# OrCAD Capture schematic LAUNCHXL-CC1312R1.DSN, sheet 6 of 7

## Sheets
6 2_Peripherals: size A3
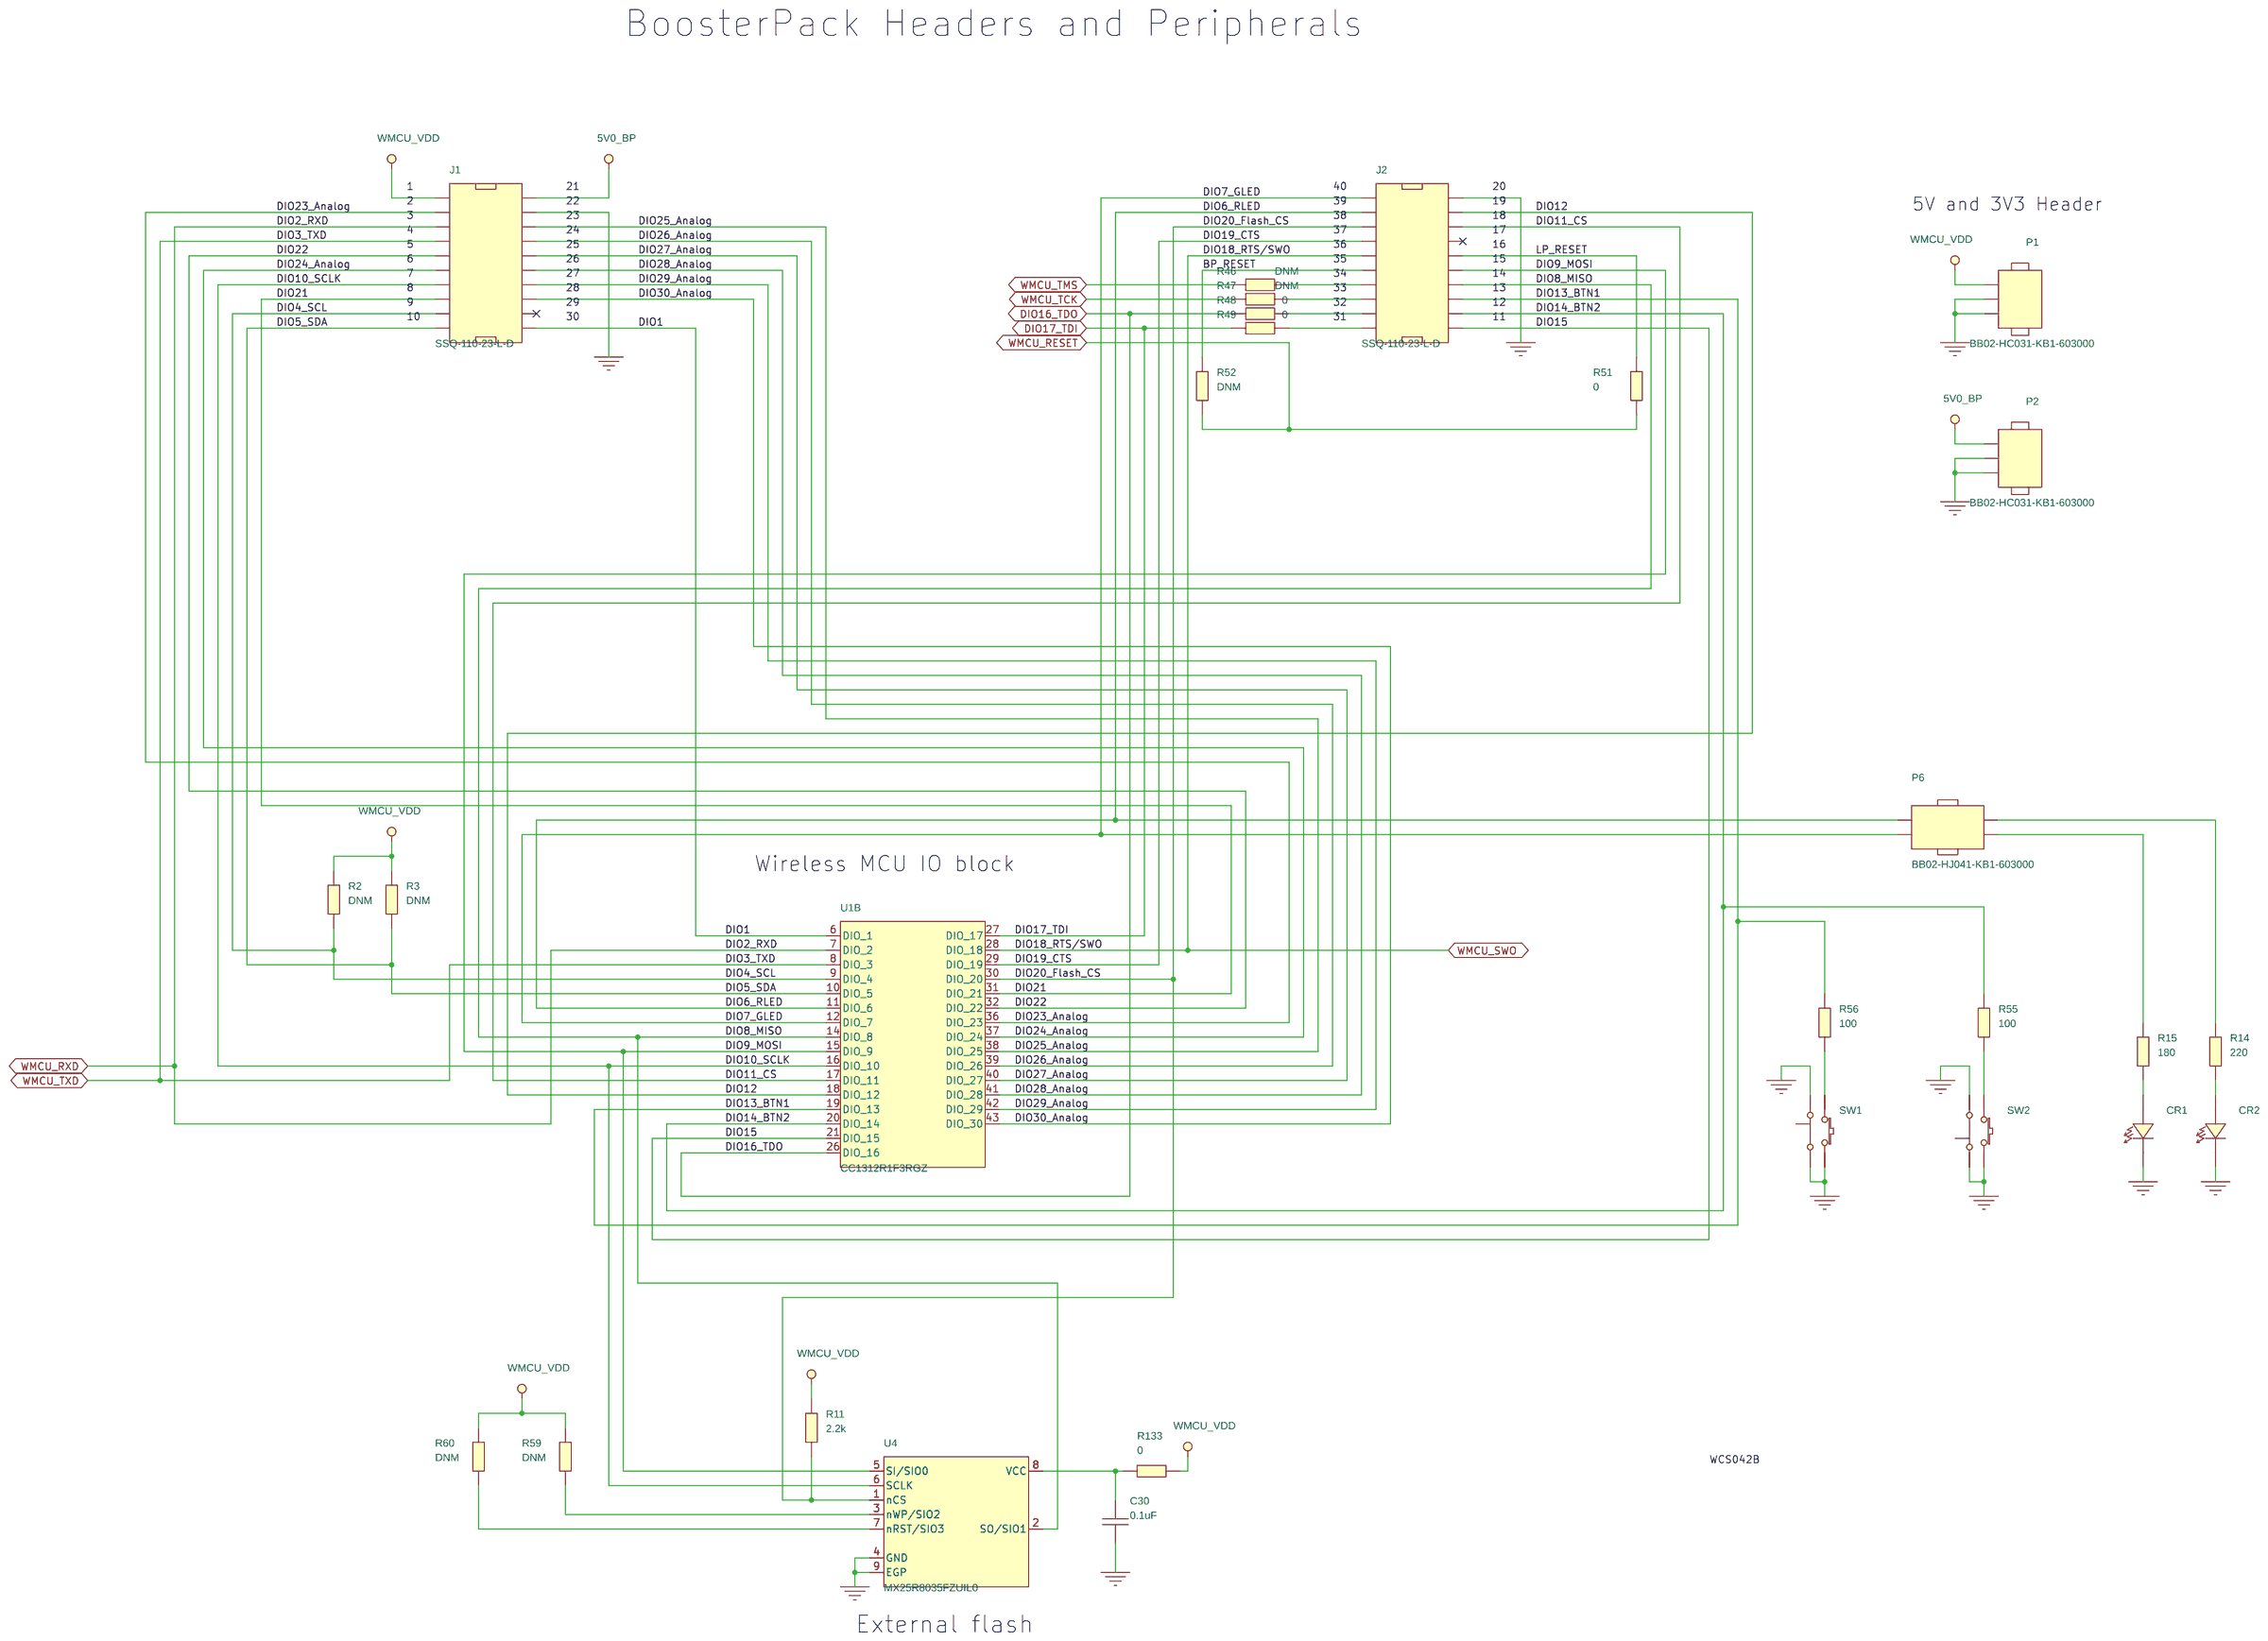
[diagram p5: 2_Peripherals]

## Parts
C30  0.1uF  [CAPC1005X60B2N]
CR1  LPL296-J2L2-25  [LEDC1707X65L]
CR2  LS L296-P2Q2-1  [LEDC1708X67L]
J1  SSQ-110-23-L-D  [SAMTEC_SSQ11023LD_A2B]
J2  SSQ-110-23-L-D  [SAMTEC_SSQ11023LD_A2B]
P1  BB02-HC031-KB1-603000  [GRADCONN_BB02HC031KB1603000_A2B]
P2  BB02-HC031-KB1-603000  [GRADCONN_BB02HC031KB1603000_A2B]
P6  BB02-HJ041-KB1-603000  [GRADCONN_BB02HJ041KB1603000_A2B]
R2  DNM  [RESC1005X40B2N]
R3  DNM  [RESC1005X40B2N]
R11  2.2k  [RESC1005X40B2N]
R14  220  [RESC1005X40B2N]
R15  180  [RESC1005X40B2N]
R46  DNM  [RESC1608X55N]
R47  DNM  [RESC1608X55N]
R48  0  [RESC1608X55A2N]
R49  0  [RESC1608X55A2N]
R51  0  [RESC1608X55N]
R52  DNM  [RESC1608X55N]
R55  100  [RESC1005X40B2N]
R56  100  [RESC1005X40B2N]
R59  DNM  [RESC1005X40B2N]
R60  DNM  [RESC1005X40B2N]
R133  0  [RESC1608X55N]
SW1  1188E-1K2-V  [SW_1188E1K2V_A2N]
SW2  1188E-1K2-V  [SW_1188E1K2V_A2N]
U1  CC1312R1F3RGZ  [QFNFC50P700X700X100-49A2N]  (sections A,B)
U4  MX25R8035FZUIL0  [SON50P300X200X60-9B2L]

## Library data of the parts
C30 = CAPACITOR: CAPACITOR, CERAMIC X7R, 0.1uF, 25V, -10%/+10%, -55DEGC/+125DEGC, 0402, SMD; AutoDoc File: https://notefied-dynamic-precision.com/DB/Apps/Desktop/Item/Object.aspx?id=115293; BU Name: TEXAS INSTRUMENTS NORWAY; Client Status: UNDER_REVIEW; Datasheet URL 1: http://psearch.en.murata.com/capacitor/product/GRM155R71E104KE14%23.pdf; Datasheet URL 2: http://search.murata.co.jp/Ceramy/image/img/w_hinm/L0005E.pdf; Definied Quality: INDUSTRIAL; Dielectric Type: X7R; Esd Level: N/A; Last Time Buy: N/A; LifeCycle Status: ACTIVE; MPN: CAPACITOR_0402_100nF_X7R_M_+/-10%_10V; MPN Status: ACTIVE; MSL: N/A; MTBF: N/A; MTBF Standard: N/A; Manufacturer: MANUFACTURER SELECTION; Max Oper Temp: +125DEGC; Max Tol: +10%; Min Oper Temp: -55DEGC; Min Tol: -10%; Mounting Type: SMD; NOTE Status: PREFERRED; Old Footprint: CAPC1005X60N; PCB Package: 0402; Packing Size: 10000; Packing Type: TAPE_&_REEL; Part Number: 02-07861; Part Type: CAPACITOR\CERAMIC\0402\STANDARD; REACH/SVHC_COMPLIANCE: COMPLIANT; REACH/SVHC_DETAILS: SVHC LIST VERSION Jun 20, 2016; REACH/SVHC_SOURCE: REACH DECLARATION; REACH/SVHC_STATUS: UNAFFECTED; Revision: R002; RoHS Status: ROHS_COMPLIANT; Rtd Voltage: 25V; Vendor: MURATA; Vendor Part Number: GRM155R71E104KE14D; Vendor Part Status: ACTIVE; WEIGHT: 0.0016g
CR1 = LED_0: OPTO, LED, GREEN COLOR, 562nm, 0.02A, 0.08W, 0603, SMD; ALT_SYMBOLS: LEDC1707X65L,LEDC1707X65M; AutoDoc File: http://notefied-dynamic-precision.com/DB/Apps/Desktop/Item/Object.aspx?id=81622; Budget Currency: USD; Budget Price: 0.1263; Datasheet URL 1: N/A; Datasheet URL 2: http://catalog.osram-os.com/jsp/download.jsp?rootPath=/media/&name=LP_L296.pdf&docPath=Graphics/00077128_0.pdf&url=/media//_en/Graphics/00077128_0.pdf; Definied Quality: INDUSTRIAL; Esd Level: HBM 2kV; FPLIST: LEDC1707X65N,LEDC1707X65L,LEDC1707X65M; Last Time Buy: N/A; Lead Time: 8; MPN: LP L296-J2L2-25; MPN Status: NRND; MSL: 2; MTBF: N/A; MTBF Standard: N/A; Manufacturer: OSRAM; Max Oper Temp: +100DEGC; Min Oper Temp: -40DEGC; Mounting Type: SMD; NOTE Status: NOT_PREFERRED; Old Footprint: LEDC1707X65N; PCB Package: 0603; Packing Size: 5000; Packing Type: TAPE_&_REEL; Part Number: 15-01023; Part Type: OPTO\LED\0603; Revision: R003; RoHS Status: ROHS_COMPLIANT; Rtd Current: 0.02A; Rtd Power: 0.08W; Rtd Voltage: 2V; WEIGHT: 0.002g
CR2 = LED_0: OPTO, LED, SUPER RED COLOR, 630nm, 1.8V TO 2.3V, 0.06A, 0603, SMD; ALT_SYMBOLS: LEDC1708X67L,LEDC1708X67M; AutoDoc File: http://notefied-dynamic-precision.com/DB/Apps/Desktop/Item/Object.aspx?id=88355; Budget Currency: USD; Budget Price: 0.089; Datasheet URL 1: http://www.osram-os.com/osram_os/en/products/product-catalog/led-light-emitting-diodes/smartled-0603/ls-l296/index.jsp?search_result=%2fosram_os%2fen%2fsearch%2fadvanced_search.jsp%3faction%3ddosearch%26inp_searchterm_1%3dLS%2bL296-P2Q2-1%26website_name%3; Datasheet URL 2: http://www.osram-os.com/Graphics/XPic5/00077119_0.pdf/LS%20L296%20-%20SMARTLED%200603.pdf; Definied Quality: INDUSTRIAL; Esd Level: HBM 2kV; FPLIST: LEDC1708X67N,LEDC1708X67L,LEDC1708X67M; Last Time Buy: N/A; Lead Time: 8; MPN Status: NRND; MSL: 2; MTBF: N/A; MTBF Standard: N/A; Manufacturer: OSRAM; Max Oper Temp: +100DEGC; Min Oper Temp: -40DEGC; Mounting Type: SMD; NOTE Status: PREFERRED; Old Footprint: LEDC1708X67N; PCB Package: 0603; PPCB Recomendation: Inactive for new design [Alert:0001]; Packing Size: 5000; Packing Type: TAPE_&_REEL; Part Number: 15-01169; Part Type: OPTO\LED\0603; Revision: R003; RoHS Status: ROHS_COMPLIANT; Rtd Current: 0.06A; Rtd Voltage: 1.8V TO 2.3V; WEIGHT: 0.002g
J1 J2 = CONN_HEADER_2X10_J_S_V1: CONNECTOR, HEADER, FEMALE, STRAIGHT, 2 ROWS, 20 ROWS, 2.54mm, PTH; ALT_SYMBOLS: SAMTEC_SSQ11023LD_A2C,SAMTEC_SSQ11023LD_A2A; AutoDoc File: http://notefied-dynamic-precision.com/DB/Apps/Desktop/Item/Object.aspx?id=104387; Budget Currency: USD; Budget Price: 2.14; Datasheet URL 1: http://suddendocs.samtec.com/prints/ssq-1xx-xx-xxx-x-xx-xxx-xx-x-mkt.pdf; Datasheet URL 2: http://suddendocs.samtec.com/catalog_english/ssq_th.pdf; Definied Quality: INDUSTRIAL; Esd Level: N/A; FPLIST: SAMTEC_SSQ11023LD_A2B,SAMTEC_SSQ11023LD_A2C,SAMTEC_SSQ11023LD_A2A; Lead Time: 1; LifeCycle Status: ACTIVE; MPN Status: ACTIVE; MSL: N/A; Manufacturer: SAMTEC; Max Oper Temp: +125DEGC; Min Oper Temp: -55DEGC; Mounting Type: PTH; NOTE Status: PREFERRED; No Of Pos: 20; No Of Rows: 2; Packing Size: 21; Packing Type: BULK; Part Number: 06-04997; Part Type: CONNECTOR\HEADER; Pitch: 2.54mm; Revision: R001; RoHS Status: ROHS_COMPLIANT; Rtd Current: 6.3A; WEIGHT: 2.45594g
P1 P2 = CONN_HEADER_3_P_S: CONNECTOR, HEADER, MALE, STRAIGHT, 1 ROW, 3 PINS, PITCH 2.54mm, PTH; ALT_SYMBOLS: GRADCONN_BB02HC031KB1603000_A2C,GRADCONN_BB02HC031KB1603000_A2A; AutoDoc File: http://notefied-dynamic-precision.com/DB/Apps/Desktop/Item/Object.aspx?id=104636; Datasheet URL 1: http://www.gradconn.com/Files/Drawings/BB02-HC.pdf; Datasheet URL 2: http://www.gradconn.com/Files/Specs/BTB-2.54mm-Header-specification.pdf; FPLIST: GRADCONN_BB02HC031KB1603000_A2B,GRADCONN_BB02HC031KB1603000_A2C,GRADCONN_BB02HC031KB1603000_A2A; MPN Status: ACTIVE; Manufacturer: GRADCONN; Max Oper Temp: +105DEGC; Min Oper Temp: -40DEGC; Mounting Type: PTH; NOTE Status: PREFERRED; No Of Pos: 3; No Of Rows: 1; Part Number: 06-05038; Part Type: CONNECTOR\HEADER; Pitch: 2.54mm; Revision: R001; RoHS Status: ROHS_COMPLIANT; Rtd Current: 3A; Rtd Voltage: 250V
P6 = CONN_HEADER_2X2_P: CONNECTOR, HEADER, MALE, STRAIGHT, 2 ROWS, 4 PINS, PITCH 2.54mm, PTH; ALT_SYMBOLS: GRADCONN_BB02HJ041KB1603000_A2C,GRADCONN_BB02HJ041KB1603000_A2A; AutoDoc File: http://notefied-dynamic-precision.com/DB/Apps/Desktop/Item/Object.aspx?id=104391; Datasheet URL 1: http://www.gradconn.com/Files/Drawings/BB02-HJ.pdf; Datasheet URL 2: http://www.gradconn.com/Files/Specs/BTB-2.54mm-Header-specification.pdf; FPLIST: GRADCONN_BB02HJ041KB1603000_A2B,GRADCONN_BB02HJ041KB1603000_A2C,GRADCONN_BB02HJ041KB1603000_A2A; MPN Status: ACTIVE; Manufacturer: GRADCONN; Max Oper Temp: +105DEGC; Min Oper Temp: -40DEGC; Mounting Type: PTH; NOTE Status: PREFERRED; No Of Pos: 4; No Of Rows: 2; Part Number: 06-04999; Part Type: CONNECTOR\HEADER; Pitch: 2.54mm; Revision: R001; RoHS Status: ROHS_COMPLIANT; Rtd Current: 3A
R2 R3 = RESISTOR: RESISTOR, THICK FILM, 3.3k, -5%/+5%, 0.063W, 50V, -55DEGC/+155DEGC, 0402, SMD; AutoDoc File: https://notefied-dynamic-precision.com/DB/Apps/Desktop/Item/Object.aspx?id=114561; BU Name: TEXAS INSTRUMENTS NORWAY; Budget Currency: EUR; Budget Price: 0.014; Client Status: UNDER_REVIEW; Country of Origin: ISRAEL; Datasheet URL 1: http://www.vishay.com/docs/20035/dcrcwe3.pdf; Datasheet URL 2: N/A; Definied Quality: INDUSTRIAL; Esd Level: N/A; Last Time Buy: N/A; Lead Time: 18; LifeCycle Status: ACTIVE; MPN: RESISTOR_0402_3.3k_+/-5%_50V_0.063W_M_+/-200ppm; MPN Status: ACTIVE; MSL: N/A; MTBF: N/A; MTBF Standard: N/A; Manufacturer: MANUFACTURER SELECTION; Max Oper Temp: +155DEGC; Max TC: +200PPM/DEGC; Max Tol: +5%; Min Oper Temp: -55DEGC; Min TC: -200PPM/DEGC; Min Tol: -5%; Mounting Type: SMD; NOTE Status: PREFERRED; Old Footprint: RESC1005X40N; PCB Package: 0402; Packing Size: 10000; Packing Type: TAPE_&_REEL; Part Number: 01-22488; Part Type: RESISTOR\0402\STANDARD; REACH/SVHC_COMPLIANCE: COMPLIANT; REACH/SVHC_DETAILS: SVHC LIST VERSION Jun 20, 2016; REACH/SVHC_SOURCE: MATERIAL DECLARATION; REACH/SVHC_STATUS: UNAFFECTED; Resistance: 3.3k; Resistor Type: THICK FILM; Revision: R000; RoHS Status: ROHS_COMPLIANT; Rtd Current: N/A; Rtd Power: 0.063W; Rtd Voltage: 50V; Vendor: VISHAY; Vendor Part Number: CRCW04023K30JNED; Vendor Part Status: ACTIVE; WEIGHT: 0.00065g
R11 = RESISTOR: RESISTOR, THICK FILM, 2.2k, -5%/+5%, 0.063W, 50V, -55DEGC/+155DEGC, 0402, SMD; AutoDoc File: https://notefied-dynamic-precision.com/DB/Apps/Desktop/Item/Object.aspx?id=114560; BU Name: TEXAS INSTRUMENTS NORWAY; Budget Currency: EUR; Budget Price: 0.014; Client Status: UNDER_REVIEW; Country of Origin: ISRAEL; Datasheet URL 1: http://www.vishay.com/docs/20035/dcrcwe3.pdf; Datasheet URL 2: N/A; Definied Quality: INDUSTRIAL; Esd Level: N/A; Last Time Buy: N/A; Lead Time: 18; LifeCycle Status: ACTIVE; MPN: RESISTOR_0402_2.2k_+/-5%_50V_0.063W_M_+/-200ppm; MPN Status: ACTIVE; MSL: N/A; MTBF: N/A; MTBF Standard: N/A; Manufacturer: MANUFACTURER SELECTION; Max Oper Temp: +155DEGC; Max TC: +200PPM/DEGC; Max Tol: +5%; Min Oper Temp: -55DEGC; Min TC: -200PPM/DEGC; Min Tol: -5%; Mounting Type: SMD; NOTE Status: PREFERRED; Old Footprint: RESC1005X40N; PCB Package: 0402; Packing Size: 10000; Packing Type: TAPE_&_REEL; Part Number: 01-22487; Part Type: RESISTOR\0402\STANDARD; REACH/SVHC_COMPLIANCE: COMPLIANT; REACH/SVHC_DETAILS: SVHC LIST VERSION Jun 20, 2016; REACH/SVHC_SOURCE: MATERIAL DECLARATION; REACH/SVHC_STATUS: UNAFFECTED; Resistor Type: THICK FILM; Revision: R000; RoHS Status: ROHS_COMPLIANT; Rtd Current: N/A; Rtd Power: 0.063W; Rtd Voltage: 50V; Vendor: VISHAY; Vendor Part Number: CRCW04022K20JNED; Vendor Part Status: ACTIVE; WEIGHT: 0.00065g
R14 = RESISTOR: RESISTOR, THICK FILM, 220, -5%/+5%, 0.063W, 50V, -55DEGC/+155DEGC, 0402, SMD; AutoDoc File: https://notefied-dynamic-precision.com/DB/Apps/Desktop/Item/Object.aspx?id=113319; BU Name: TEXAS INSTRUMENTS NORWAY; Budget Currency: EUR; Budget Price: 0.014; Client Status: UNDER_REVIEW; Country of Origin: ISRAEL; Datasheet URL 1: http://www.vishay.com/docs/20035/dcrcwe3.pdf; Datasheet URL 2: N/A; Definied Quality: INDUSTRIAL; Esd Level: N/A; Last Time Buy: N/A; Lead Time: 18; LifeCycle Status: ACTIVE; MPN: RESISTOR_0402_220_+/-5%_50V_0.063W_M_+/-200ppm; MPN Status: ACTIVE; MSL: N/A; MTBF: N/A; MTBF Standard: N/A; Manufacturer: MANUFACTURER SELECTION; Max Oper Temp: +155DEGC; Max TC: +200PPM/DEGC; Max Tol: +5%; Min Oper Temp: -55DEGC; Min TC: -200PPM/DEGC; Min Tol: -5%; Mounting Type: SMD; NOTE Status: PREFERRED; Old Footprint: RESC1005X40N; PCB Package: 0402; Packing Size: 10000; Packing Type: TAPE_&_REEL; Part Number: 01-22346; Part Type: RESISTOR\0402\STANDARD; REACH/SVHC_COMPLIANCE: COMPLIANT; REACH/SVHC_DETAILS: SVHC LIST VERSION Jun 20, 2016; REACH/SVHC_SOURCE: MATERIAL DECLARATION; REACH/SVHC_STATUS: UNAFFECTED; Resistor Type: THICK FILM; Revision: R001; RoHS Status: ROHS_COMPLIANT_WITH_EXEMPTION; Rtd Current: N/A; Rtd Power: 0.063W; Rtd Voltage: 50V; Vendor: VISHAY; Vendor Part Number: CRCW0402220RJNED; Vendor Part Status: ACTIVE; WEIGHT: 0.00065g
R15 = RESISTOR: RESISTOR, THICK FILM, 180, -5%/+5%, 0.063W, 50V, -55DEGC/+155DEGC, 0402, SMD; AutoDoc File: https://notefied-dynamic-precision.com/DB/Apps/Desktop/Item/Object.aspx?id=113318; BU Name: TEXAS INSTRUMENTS NORWAY; Budget Currency: EUR; Budget Price: 0.014; Client Status: UNDER_REVIEW; Country of Origin: MISSING INFO; Datasheet URL 1: http://www.vishay.com/docs/20035/dcrcwe3.pdf; Datasheet URL 2: N/A; Definied Quality: INDUSTRIAL; Esd Level: N/A; Last Time Buy: N/A; Lead Time: 18; LifeCycle Status: ACTIVE; MPN: RESISTOR_0402_180_+/-5%_50V_0.063W_M_+/-200ppm; MPN Status: ACTIVE; MSL: N/A; MTBF: N/A; MTBF Standard: N/A; Manufacturer: MANUFACTURER SELECTION; Max Oper Temp: +155DEGC; Max TC: +200PPM/DEGC; Max Tol: +5%; Min Oper Temp: -55DEGC; Min TC: -200PPM/DEGC; Min Tol: -5%; Mounting Type: SMD; NOTE Status: PREFERRED; Old Footprint: RESC1005X40N; PCB Package: 0402; Packing Size: 10000; Packing Type: TAPE_&_REEL; Part Number: 01-22345; Part Type: RESISTOR\0402\STANDARD; REACH/SVHC_COMPLIANCE: COMPLIANT; REACH/SVHC_DETAILS: SVHC LIST VERSION Jun 20, 2016; REACH/SVHC_SOURCE: MATERIAL DECLARATION; REACH/SVHC_STATUS: UNAFFECTED; Resistor Type: THICK FILM; Revision: R001; RoHS Status: ROHS_COMPLIANT_WITH_EXEMPTION; Rtd Current: N/A; Rtd Power: 0.063W; Rtd Voltage: 50V; Vendor: VISHAY; Vendor Part Number: CRCW0402180RJNED; Vendor Part Status: ACTIVE; WEIGHT: 0.00065g
R46 R47 = RESISTOR: RESISTOR, DO NOT MOUNT, 0603, SMD; ALT_SYMBOLS: RESC1608X55L,RESC1608X55M; AutoDoc File: http://notefied-dynamic-precision.com/DB/Apps/Desktop/Item/Object.aspx?id=48377; Budget Currency: N/A; Budget Price: N/A; Datasheet URL 1: N/A; Datasheet URL 2: N/A; Esd Level: N/A; FPLIST: RESC1608X55N,RESC1608X55L,RESC1608X55M; Last Time Buy: N/A; Lead Time: N/A; LifeCycle Status: ACTIVE; MPN Status: ACTIVE; MSL: N/A; MTBF: N/A; MTBF Standard: N/A; Manufacturer: DO NOT MOUNT; Max Oper Temp: N/A; Max TC: N/A; Max Tol: N/A; Min Oper Temp: N/A; Min TC: N/A; Min Tol: N/A; Mounting Type: SMD; NOTE Status: PREFERRED; Old Footprint: RESC1608X55N,0603; PCB Package: 0603; Packing Size: N/A; Part Number: 01-02493; Part Type: RESISTOR\0603\STANDARD; Resistor Type: N/A; Revision: R001; RoHS Status: MISSING_INFO; Rtd Current: N/A; Rtd Power: N/A; Rtd Voltage: N/A; WEIGHT: N/A
R48 R49 = RESISTOR: RESISTOR, THICK FILM, 0, 0R/+0.02R, 0.1W, 75V, -55DEGC/+155DEGC, 0603, SMD; ALT_SYMBOLS: RESC1608X55A2L,RESC1608X55A2M; AutoDoc File: https://notefied-dynamic-precision.com/DB/Apps/Desktop/Item/Object.aspx?id=94847; BU Name: DYNAMIC PRECISION GDANSK; Budget Currency: USD; Budget Price: 0.0016; Client Status: UNDER_REVIEW; Country of Origin: ISRAEL; Datasheet URL 1: http://www.vishay.com/docs/20035/dcrcwe3.pdf; Datasheet URL 2: N/A; Esd Level: N/A; Last Time Buy: N/A; Lead Time: 12; LifeCycle Status: ACTIVE; MPN: DNM; MPN Status: ACTIVE; MSL: N/A; MTBF: N/A; MTBF Standard: N/A; Manufacturer: DO NOT MOUNT; Max Oper Temp: +155DEGC; Max TC: N/A; Max Tol: +0.02R; Min Oper Temp: -55DEGC; Min TC: N/A; Min Tol: 0R; Mounting Type: SMD; NOTE Status: PREFERRED; Old Footprint: RESC1608X55N,0603; PCB Package: 0603; Packing Size: 20000; Packing Type: TAPE_&_REEL; Part Number: 01-20043; Part Type: RESISTOR\0603\JUMPER; REACH/SVHC_COMPLIANCE: COMPLIANT; REACH/SVHC_DETAILS: SVHC LIST VERSION Jun 15, 2015; REACH/SVHC_SOURCE: MATERIAL DECLARATION; REACH/SVHC_STATUS: UNAFFECTED; Resistor Type: THICK FILM; Revision: R002; RoHS Status: ROHS_COMPLIANT_WITH_EXEMPTION; Rtd Current: N/A; Rtd Power: 0.1W; Rtd Voltage: 75V; Vendor: VISHAY; Vendor Part Number: CRCW06030000Z0EC; Vendor Part Status: ACTIVE; WEIGHT: 0.002g
R51 R133 = RESISTOR: RESISTOR, THICK FILM, 0, 0R/+0.02R, 0.1W, 75V, -55DEGC/+155DEGC, 0603, SMD; ALT_SYMBOLS: RESC1608X55L,RESC1608X55M; AutoDoc File: https://notefied-dynamic-precision.com/DB/Apps/Desktop/Item/Object.aspx?id=94847; BU Name: DYNAMIC PRECISION GDANSK; Budget Currency: USD; Budget Price: 0.0016; Client Status: UNDER_REVIEW; Country of Origin: ISRAEL; Datasheet URL 1: http://www.vishay.com/docs/20035/dcrcwe3.pdf; Datasheet URL 2: N/A; Esd Level: N/A; Last Time Buy: N/A; Lead Time: 12; LifeCycle Status: ACTIVE; MPN: DNM; MPN Status: ACTIVE; MSL: N/A; MTBF: N/A; MTBF Standard: N/A; Manufacturer: DO NOT MOUNT; Max Oper Temp: +155DEGC; Max TC: N/A; Max Tol: +0.02R; Min Oper Temp: -55DEGC; Min TC: N/A; Min Tol: 0R; Mounting Type: SMD; NOTE Status: PREFERRED; Old Footprint: RESC1608X55N,0603; PCB Package: 0603; Packing Size: 20000; Packing Type: TAPE_&_REEL; Part Number: 01-20043; Part Type: RESISTOR\0603\JUMPER; REACH/SVHC_COMPLIANCE: COMPLIANT; REACH/SVHC_DETAILS: SVHC LIST VERSION Jun 15, 2015; REACH/SVHC_SOURCE: MATERIAL DECLARATION; REACH/SVHC_STATUS: UNAFFECTED; Resistor Type: THICK FILM; Revision: R001; RoHS Status: ROHS_COMPLIANT_WITH_EXEMPTION; Rtd Current: N/A; Rtd Power: 0.1W; Rtd Voltage: 75V; Vendor: VISHAY; Vendor Part Number: CRCW06030000Z0EC; Vendor Part Status: ACTIVE; WEIGHT: 0.002g
R52 = RESISTOR: RESISTOR, THICK FILM, 0, 0R/+0.02R, 0.1W, 75V, -55DEGC/+155DEGC, 0603, SMD; ALT_SYMBOLS: RESC1608X55L,RESC1608X55M; AutoDoc File: https://notefied-dynamic-precision.com/DB/Apps/Desktop/Item/Object.aspx?id=94847; BU Name: DYNAMIC PRECISION GDANSK; Budget Currency: USD; Budget Price: 0.0016; Client Status: UNDER_REVIEW; Country of Origin: ISRAEL; Datasheet URL 1: http://www.vishay.com/docs/20035/dcrcwe3.pdf; Datasheet URL 2: N/A; Esd Level: N/A; Last Time Buy: N/A; Lead Time: 12; LifeCycle Status: ACTIVE; MPN Status: ACTIVE; MSL: N/A; MTBF: N/A; MTBF Standard: N/A; Manufacturer: DO NOT MOUNT; Max Oper Temp: +155DEGC; Max TC: N/A; Max Tol: +0.02R; Min Oper Temp: -55DEGC; Min TC: N/A; Min Tol: 0R; Mounting Type: SMD; NOTE Status: PREFERRED; Old Footprint: RESC1608X55N,0603; PCB Package: 0603; Packing Size: 20000; Packing Type: TAPE_&_REEL; Part Number: 01-20043; Part Type: RESISTOR\0603\JUMPER; REACH/SVHC_COMPLIANCE: COMPLIANT; REACH/SVHC_DETAILS: SVHC LIST VERSION Jun 15, 2015; REACH/SVHC_SOURCE: MATERIAL DECLARATION; REACH/SVHC_STATUS: UNAFFECTED; Resistance: 0; Resistor Type: THICK FILM; Revision: R001; RoHS Status: ROHS_COMPLIANT_WITH_EXEMPTION; Rtd Current: N/A; Rtd Power: 0.1W; Rtd Voltage: 75V; Vendor: VISHAY; Vendor Part Number: CRCW06030000Z0EC; Vendor Part Status: ACTIVE; WEIGHT: 0.002g
R55 R56 = RESISTOR: RESISTOR, THICK FILM, 100, -5%/+5%, 0.063W, 50V, -55DEGC/+155DEGC, 0402, SMD; AutoDoc File: https://notefied-dynamic-precision.com/DB/Apps/Desktop/Item/Object.aspx?id=114555; BU Name: TEXAS INSTRUMENTS NORWAY; Budget Currency: USD; Budget Price: 0.0014; Client Status: UNDER_REVIEW; Country of Origin: UNITED STATES; Datasheet URL 1: http://www.vishay.com/docs/20035/dcrcwe3.pdf; Datasheet URL 2: N/A; Definied Quality: INDUSTRIAL; Esd Level: N/A; Last Time Buy: N/A; Lead Time: 16; LifeCycle Status: ACTIVE; MPN: RESISTOR_0402_100_+/-5%_50V_0.063W_M_+/-200ppm; MPN Status: ACTIVE; MSL: N/A; MTBF: N/A; MTBF Standard: N/A; Manufacturer: MANUFACTURER SELECTION; Max Oper Temp: +155DEGC; Max TC: +200PPM/DEGC; Max Tol: +5%; Min Oper Temp: -55DEGC; Min TC: -200PPM/DEGC; Min Tol: -5%; Mounting Type: SMD; NOTE Status: PREFERRED; Old Footprint: RESC1005X40N; PCB Package: 0402; Packing Size: 10000; Packing Type: TAPE_&_REEL; Part Number: 01-22482; Part Type: RESISTOR\0402\STANDARD; REACH/SVHC_COMPLIANCE: COMPLIANT; REACH/SVHC_DETAILS: SVHC LIST VERSION Jun 20, 2016; REACH/SVHC_SOURCE: MATERIAL DECLARATION; REACH/SVHC_STATUS: UNAFFECTED; Resistor Type: THICK FILM; Revision: R000; RoHS Status: ROHS_COMPLIANT; Rtd Current: N/A; Rtd Power: 0.063W; Rtd Voltage: 50V; Vendor: VISHAY; Vendor Part Number: CRCW0402100RJNED; Vendor Part Status: ACTIVE; WEIGHT: 0.00065g
R59 R60 = RESISTOR: RESISTOR, DO NOT MOUNT, 0402, SMD; AutoDoc File: https://notefied-dynamic-precision.com/DB/Apps/Desktop/Item/Object.aspx?id=113312; BU Name: TEXAS INSTRUMENTS NORWAY; Budget Currency: N/A; Budget Price: N/A; Country of Origin: MISSING INFO; Datasheet URL 1: N/A; Datasheet URL 2: N/A; Esd Level: N/A; Last Time Buy: N/A; Lead Time: N/A; LifeCycle Status: ACTIVE; MPN Status: ACTIVE; MSL: N/A; MTBF: N/A; MTBF Standard: N/A; Manufacturer: DO NOT MOUNT; Max Oper Temp: N/A; Max TC: N/A; Max Tol: N/A; Min Oper Temp: N/A; Min TC: N/A; Min Tol: N/A; Mounting Type: SMD; NOTE Status: PREFERRED; Old Footprint: RESC1005X40N,0402; PCB Package: 0402; Packing Size: N/A; Part Number: 01-22339; Part Type: RESISTOR\0402\STANDARD; Resistance: N/A; Resistor Type: THICK FILM; Revision: R000; RoHS Status: MISSING_INFO; Rtd Current: N/A; Rtd Power: N/A; Rtd Voltage: N/A; Vendor: DO NOT MOUNT; Vendor Part Status: ACTIVE; WEIGHT: N/A
SW1 SW2 = SWITCH_TACT_V2: SWITCH, TACT, 0.05A@250VAC, 0.05A@12VDC, 0.05A, 250V, SMD; ALT_SYMBOLS: SW_1188E1K2V_A2L,SW_1188E1K2V_A2M; AutoDoc File: http://notefied-dynamic-precision.com/DB/Apps/Desktop/Item/Object.aspx?id=104642; Datasheet URL 1: N/A; Datasheet URL 2: http://www.dip.com.tw/en/en-product-information/en-switch004; FPLIST: SW_1188E1K2V_A2N,SW_1188E1K2V_A2L,SW_1188E1K2V_A2M; MPN: 1188E-1K2-V-TR; MPN Status: ACTIVE; Manufacturer: DIPTRONICS; Max Oper Temp: +70DEGC; Min Oper Temp: -25DEGC; Mounting Type: SMD; NOTE Status: PREFERRED; Packing Size: 1500; Packing Type: TAPE_&_REEL; Part Number: 08-00293; Part Type: SWITCH\TACT; Revision: R001; RoHS Status: ROHS_COMPLIANT; Rtd Current: 0.05A; Rtd Voltage: 12V
U1 = IC_RF_CC1312R1F3_VQFN48: IC, MICROCONTROLLER, TEXAS INSTRUMENTS, CUSTOM, CC1312R1F3RGZ, 1.8V TO 3.8V, VQFN48, SMD; ALT_SYMBOLS: QFNFC50P700X700X100-49A2L,QFNFC50P700X700X100-49A2M; Additional Datasheet URL: N/A; Datasheet URL: http://www.ti.com/lit/ml/mpqf123e/mpqf123e.pdf; Exclusive for Customers: TEXAS INSTRUMENTS NORWAY; Maximum Operating Temperature: +85DEGC; Minimum Operating Temperature: -40DEGC; Mounting Type: SMD; NOTEfied URL: https://notefied-dynamic-precision.com/NOTEfiedWebInterface/part/show?partNumber=18-33969; Notes: Custom component; PCB Package: VQFN48; Part Number: 18-33969; Part Type: IC|MICROCONTROLLER|TEXAS INSTRUMENTS; REACH/SVHC Compliance: Compliant; REACH/SVHC Details: SVHC List Version Jan 12, 2017; REACH/SVHC Source: REACH Declaration; REACH/SVHC Status: Unaffected; ROHS: Compliant; Rated Voltage: 1.8V TO 3.8V; Revision: R004; Status: Released; Texas Part Status: Under Review; Type: IC; Vendor: TEXAS INSTRUMENTS; Vendor Part Status: Preliminary
U4 = IC_FLASH_MX25R8035F_USON8: IC, MEMORY, FLASH, SERIAL, 8Mbit, 1.65V TO 3.6V, USON8, SMD; ALT_SYMBOLS: SON50P300X200X60-9B2L,SON50P300X200X60-9B2M; AutoDoc File: http://notefied-dynamic-precision.com/DB/Apps/Desktop/Item/Object.aspx?id=104624; Datasheet URL 1: N/A; Datasheet URL 2: http://www.macronix.com/Lists/DataSheet/Attachments/2570/MX25R8035F,%20Wide%20Range,%208Mb,%20v0.04.pdf; FPLIST: SON50P300X200X60-9B2N,SON50P300X200X60-9B2L,SON50P300X200X60-9B2M; MPN Status: ACTIVE; Manufacturer: MACRONIX; Max Oper Temp: +85DEGC; Min Oper Temp: -40DEGC; Mounting Type: SMD; NOTE Status: PREFERRED; Old Footprint: SON50P300X200X60-9B2N; PCB Package: USON8; Part Number: 18-31726; Part Type: IC\MEMORY\FLASH\OTHER; Revision: R001; RoHS Status: ROHS_COMPLIANT; Rtd Voltage: 1.65V TO 3.6V

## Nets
5V0_BP: J1.2 P2.1 ; also on sheet 4
GND: C30.2 CR1.1(C) CR2.1(C) J1.4 J2.2 P1.2 P1.3 P2.2 P2.3 SW1.1 SW1.2 SW1.3 SW2.1 SW2.2 SW2.4 U4.4(GND) U4.9(EGP) ; also on sheet 1 2 3 4 5 7
BP_RESET: J2.11 R52.1
DIO1: J1.20 U1.6(DIO_1)
DIO4_SCL: J1.17 R2.1 U1.9(DIO_4)
DIO5_SDA: J1.19 R3.1 U1.10(DIO_5)
DIO6_RLED: J2.3 P6.2 U1.11(DIO_6)
DIO7_GLED: J2.1 P6.4 U1.12(DIO_7)
DIO8_MISO: J2.14 U1.14(DIO_8) U4.2(SO/SIO1)
DIO9_MOSI: J2.12 U1.15(DIO_9) U4.5(SI/SIO0)
DIO10_SCLK: J1.13 U1.16(DIO_10) U4.6(SCLK)
DIO11_CS: J2.6 U1.17(DIO_11)
DIO12: J2.4 U1.18(DIO_12)
DIO13_BTN1: J2.16 R56.2 U1.19(DIO_13)
DIO14_BTN2: J2.18 R55.2 U1.20(DIO_14)
DIO15: J2.20 U1.21(DIO_15)
DIO16_TDO: R48.2 U1.26(DIO_16) ; also on sheet 4
DIO17_TDI: R49.2 U1.27(DIO_17) ; also on sheet 4
DIO19_CTS: J2.7 U1.29(DIO_19)
DIO20_Flash_CS: J2.5 R11.1 U1.30(DIO_20) U4.1(nCS)
DIO21: J1.15 U1.31(DIO_21)
DIO22: J1.9 U1.32(DIO_22)
DIO23_Analog: J1.3 U1.36(DIO_23)
DIO24_Analog: J1.11 U1.37(DIO_24)
DIO25_Analog: J1.6 U1.38(DIO_25)
DIO26_Analog: J1.8 U1.39(DIO_26)
DIO27_Analog: J1.10 U1.40(DIO_27)
DIO28_Analog: J1.12 U1.41(DIO_28)
DIO29_Analog: J1.14 U1.42(DIO_29)
DIO30_Analog: J1.16 U1.43(DIO_30)
LP_RESET: J2.10 R51.1
WMCU_RESET: R51.2 R52.2 ; also on sheet 4 7
WMCU_RXD: J1.5 U1.7(DIO_2) ; also on sheet 4
WMCU_SWO: J2.9 U1.28(DIO_18) ; also on sheet 4
WMCU_TCK: R47.2 ; also on sheet 4 7
WMCU_TMS: R46.2 ; also on sheet 4 7
WMCU_TXD: J1.7 U1.8(DIO_3) ; also on sheet 4
WMCU_VDD: J1.1 P1.1 R2.2 R3.2 R11.2 R59.2 R60.2 R133.2 ; also on sheet 4 7
N1017630: C30.1 R133.1 U4.8(VCC)
N1105722: CR1.2(A) R15.1
N1105771: CR2.2(A) R14.1
N1105824: P6.1 R14.2
N1106228: P6.3 R15.2
N1176544: J2.13 R46.1
N1176548: J2.15 R47.1
N1176568: J2.17 R48.1
N1177007: J2.19 R49.1
N1288065: R55.1 SW2.3
N1288098: R56.1 SW1.4
N1409884: R59.1 U4.3(nWP/SIO2)
N1409917: R60.1 U4.7(nRST/SIO3)

Not connected (* = marked no-connect by the designer): J1 18*; J2 8*

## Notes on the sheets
sheet 6
- BoosterPack Headers and Peripherals
- 1
- 21
- 40
- 20
- 2
- 22
- 39
- 19
- 5V and 3V3 Header
- 3
- 23
- 38
- 18
- 4
- 24
- 37
- 17
- 5
- 6
- 25
- 26
- 35
- 36
- 15
- 16
- 7
- 27
- 34
- 14
- 8
- 28
- 33
- 13
- 9
- 29
- 32
- 12
- 10
- 30
- 31
- 11
- Wireless MCU IO block
- WCS042B
- External flash
